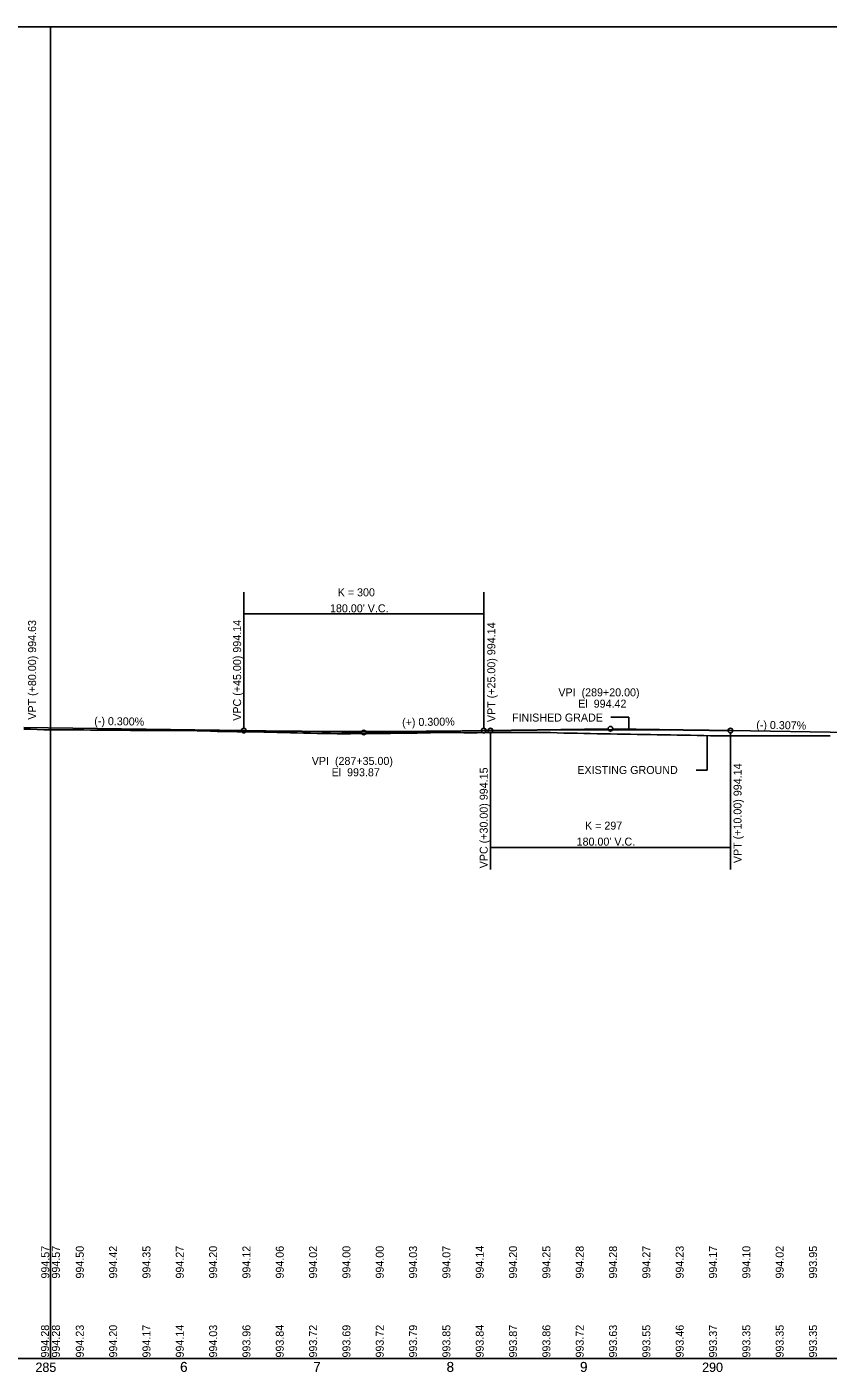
# Model space of a CAD drawing. Extents: x 1608361 to 16979326, y 1092015 to 12565288.
# Drawn here: x 16977468 to 16978069, y 12564278 to 12565286 of the extents above; entities that cross this region are included whole.
import ezdxf

# ---------------------------------------------------------------- set-up
doc = ezdxf.new("R2010")
doc.units = 0
for name, color, linetype in [('CLS_Median', 7, 'Continuous'), ('Default', 7, 'Continuous'), ('points EP', 7, 'Continuous'), ('RD_DDB_EX_Tx', 7, 'Continuous'), ('RD_EX_Fence_ChLk', 7, 'Continuous'), ('RD_EX_H2O', 7, 'Continuous'), ('RD_EX_RW_Approx', 7, 'Continuous'), ('RD_EX_SU_Water', 7, 'Continuous'), ('RD_EX_UT', 7, 'Continuous'), ('RD_HC_TX_Rel_Sta50', 7, 'Continuous'), ('RD_PD_Final_TX', 7, 'Continuous'), ('TEXT2', 7, 'Continuous')]:
    doc.layers.add(name, color=color, linetype=linetype)

msp = doc.modelspace()

# ---------------------------------------------------------------- linework, layer by layer
at = {"layer": 'CLS_Median'}
for p, q in [((16977906, 12564768.6), (16977919.4, 12564768.6)), ((16977919.4, 12564768.6), (16977919.4, 12564759.2))]:
    msp.add_line(p, q, dxfattribs=at)
at = {"layer": 'Default'}
for points in [[(16975985.6, 12564287.8), (16977485.6, 12564287.8), (16977485.6, 12565286), (16975985.6, 12565286)], [(16977485.6, 12564287.8), (16978985.6, 12564287.8), (16978985.6, 12565286), (16977485.6, 12565286)]]:
    msp.add_lwpolyline(points, close=True, dxfattribs=at)
at = {"layer": 'RD_DDB_EX_Tx'}
for p, q in [((16977978.2, 12564729), (16977978.2, 12564754.7)), ((16977970, 12564729), (16977978.2, 12564729))]:
    msp.add_line(p, q, dxfattribs=at)
at = {"layer": 'RD_EX_Fence_ChLk'}
for p, q in [((16977630.6, 12564862.3), (16977630.6, 12564760.2)), ((16977810.6, 12564862.3), (16977810.6, 12564760.2)), ((16977630.6, 12564846), (16977810.6, 12564846)), ((16977815.6, 12564654.3), (16977815.6, 12564756.8)), ((16977995.6, 12564654.3), (16977995.6, 12564756.8)), ((16977815.6, 12564671), (16977995.6, 12564671))]:
    msp.add_line(p, q, dxfattribs=at)
for centre in [(16977630.6, 12564758.5), (16977810.6, 12564758.5), (16977815.6, 12564758.5), (16977995.6, 12564758.5)]:
    msp.add_circle(centre, 1.75, dxfattribs=at)
at = {"layer": 'RD_EX_H2O'}
for points in [[(16977465.6, 12564759.6), (16977470.6, 12564759.5), (16977475.6, 12564759.3), (16977480.6, 12564759.2), (16977485.6, 12564759.2)], [(16977485.6, 12564759.2), (16977490.6, 12564759.1), (16977495.6, 12564759.1), (16977500.6, 12564759), (16977505.6, 12564759), (16977510.6, 12564759), (16977515.6, 12564758.9), (16977520.6, 12564758.9), (16977525.6, 12564758.9), (16977530.6, 12564758.8), (16977535.6, 12564758.8), (16977540.6, 12564758.8), (16977545.6, 12564758.7), (16977550.6, 12564758.7), (16977555.6, 12564758.7), (16977560.6, 12564758.7), (16977565.6, 12564758.6), (16977570.6, 12564758.6), (16977575.6, 12564758.6), (16977580.6, 12564758.5), (16977585.6, 12564758.5), (16977590.6, 12564758.5), (16977595.6, 12564758.4), (16977600.6, 12564758.3), (16977605.6, 12564758.1), (16977610.6, 12564757.9), (16977615.6, 12564757.9), (16977620.6, 12564757.8), (16977625.6, 12564757.7), (16977630.6, 12564757.6), (16977635.6, 12564757.6), (16977640.6, 12564757.5), (16977645.6, 12564757.4), (16977650.6, 12564757.3), (16977655.6, 12564757.2), (16977660.6, 12564757), (16977665.6, 12564756.9), (16977670.6, 12564756.8), (16977675.6, 12564756.6), (16977680.6, 12564756.5), (16977685.6, 12564756.4), (16977690.6, 12564756.4), (16977695.6, 12564756.3), (16977700.6, 12564756.2), (16977705.6, 12564756.2), (16977710.6, 12564756.2), (16977715.6, 12564756.3), (16977720.6, 12564756.3), (16977725.6, 12564756.3), (16977730.6, 12564756.3), (16977735.6, 12564756.4), (16977740.6, 12564756.4), (16977745.6, 12564756.6), (16977750.6, 12564756.7), (16977755.6, 12564756.7), (16977760.6, 12564756.7), (16977765.6, 12564756.8), (16977770.6, 12564756.9), (16977775.6, 12564757), (16977780.6, 12564757), (16977785.6, 12564757.1), (16977790.6, 12564757), (16977795.6, 12564756.9), (16977800.6, 12564756.9), (16977805.6, 12564756.9), (16977810.6, 12564757), (16977815.6, 12564757), (16977820.6, 12564757), (16977825.6, 12564757), (16977830.6, 12564757.1), (16977835.6, 12564757.1), (16977840.6, 12564757.1), (16977845.6, 12564757.1), (16977850.6, 12564757.1), (16977855.6, 12564757.1), (16977860.6, 12564757.1), (16977865.6, 12564756.9), (16977870.6, 12564756.7), (16977875.6, 12564756.6), (16977880.6, 12564756.5), (16977885.6, 12564756.4), (16977890.6, 12564756.3), (16977895.6, 12564756.2), (16977900.6, 12564756.1), (16977905.6, 12564756), (16977910.6, 12564755.9), (16977915.6, 12564755.9), (16977920.6, 12564755.8), (16977925.6, 12564755.7), (16977930.6, 12564755.6), (16977935.6, 12564755.5), (16977940.6, 12564755.4), (16977945.6, 12564755.3), (16977950.6, 12564755.3), (16977955.6, 12564755.2), (16977960.6, 12564755.1), (16977965.6, 12564755), (16977970.6, 12564754.9), (16977975.6, 12564754.8), (16977980.6, 12564754.7), (16977985.6, 12564754.7)], [(16977985.6, 12564754.7), (16977990.6, 12564754.6), (16977995.6, 12564754.5), (16978000.6, 12564754.5), (16978005.6, 12564754.5), (16978010.6, 12564754.5), (16978015.6, 12564754.5), (16978020.6, 12564754.5), (16978025.6, 12564754.5), (16978030.6, 12564754.5), (16978035.6, 12564754.5), (16978040.6, 12564754.5), (16978045.6, 12564754.5), (16978050.6, 12564754.5), (16978055.6, 12564754.5), (16978060.6, 12564754.5), (16978065.6, 12564754.5), (16978070.6, 12564754.5)]]:
    msp.add_lwpolyline(points, dxfattribs=at)
at = {"layer": 'RD_EX_RW_Approx'}
for p, q in [((16977630.6, 12564758.5), (16977718.8, 12564757.1)), ((16977810.5, 12564758.5), (16977722.3, 12564757.1)), ((16977815.6, 12564758.5), (16977903.8, 12564759.9)), ((16977995.5, 12564758.5), (16977907.3, 12564759.9))]:
    msp.add_line(p, q, dxfattribs=at)
for centre in [(16977720.6, 12564757.1), (16977905.6, 12564759.9)]:
    msp.add_circle(centre, 1.75, dxfattribs=at)
at = {"layer": 'RD_EX_UT'}
msp.add_line((16972985.6, 12564287.8), (16978789.9, 12564287.8), dxfattribs=at)
at = {"layer": 'RD_HC_TX_Rel_Sta50'}
for p, q in [((16977465.6, 12564760.9), (16977630.6, 12564758.5)), ((16977810.6, 12564758.5), (16977815.6, 12564758.5)), ((16977995.6, 12564758.5), (16978085.6, 12564757.1))]:
    msp.add_line(p, q, dxfattribs=at)
for points in [[(16977630.6, 12564758.5), (16977634.2, 12564758.4), (16977637.8, 12564758.4), (16977641.4, 12564758.3), (16977645, 12564758.3), (16977648.6, 12564758.2), (16977652.2, 12564758.2), (16977655.8, 12564758.1), (16977659.4, 12564758.1), (16977663, 12564758.1), (16977666.6, 12564758), (16977670.2, 12564758), (16977673.8, 12564758), (16977677.4, 12564757.9), (16977681, 12564757.9), (16977684.6, 12564757.9), (16977688.2, 12564757.9), (16977691.8, 12564757.9), (16977695.4, 12564757.8), (16977699, 12564757.8), (16977702.6, 12564757.8), (16977706.2, 12564757.8), (16977709.8, 12564757.8), (16977713.4, 12564757.8), (16977717, 12564757.8), (16977720.6, 12564757.8), (16977724.2, 12564757.8), (16977727.8, 12564757.8), (16977731.4, 12564757.8), (16977735, 12564757.8), (16977738.6, 12564757.8), (16977742.2, 12564757.8), (16977745.8, 12564757.8), (16977749.4, 12564757.9), (16977753, 12564757.9), (16977756.6, 12564757.9), (16977760.2, 12564757.9), (16977763.8, 12564757.9), (16977767.4, 12564758), (16977771, 12564758), (16977774.6, 12564758), (16977778.2, 12564758.1), (16977781.8, 12564758.1), (16977785.4, 12564758.1), (16977789, 12564758.2), (16977792.6, 12564758.2), (16977796.2, 12564758.3), (16977799.8, 12564758.3), (16977803.4, 12564758.4), (16977807, 12564758.4), (16977810.6, 12564758.5)], [(16977815.6, 12564758.5), (16977819.2, 12564758.6), (16977822.8, 12564758.6), (16977826.4, 12564758.7), (16977830, 12564758.7), (16977833.6, 12564758.8), (16977837.2, 12564758.8), (16977840.8, 12564758.9), (16977844.4, 12564758.9), (16977848, 12564758.9), (16977851.6, 12564759), (16977855.2, 12564759), (16977858.8, 12564759), (16977862.4, 12564759.1), (16977866, 12564759.1), (16977869.6, 12564759.1), (16977873.2, 12564759.1), (16977876.8, 12564759.1), (16977880.4, 12564759.2), (16977884, 12564759.2), (16977887.6, 12564759.2), (16977891.2, 12564759.2), (16977894.8, 12564759.2), (16977898.4, 12564759.2), (16977902, 12564759.2), (16977905.6, 12564759.2), (16977909.2, 12564759.2), (16977912.8, 12564759.2), (16977916.4, 12564759.2), (16977920, 12564759.2), (16977923.6, 12564759.2), (16977927.2, 12564759.2), (16977930.8, 12564759.2), (16977934.4, 12564759.1), (16977938, 12564759.1), (16977941.6, 12564759.1), (16977945.2, 12564759.1), (16977948.8, 12564759), (16977952.4, 12564759), (16977956, 12564759), (16977959.6, 12564759), (16977963.2, 12564758.9), (16977966.8, 12564758.9), (16977970.4, 12564758.8), (16977974, 12564758.8), (16977977.6, 12564758.8), (16977981.2, 12564758.7), (16977984.8, 12564758.7), (16977988.4, 12564758.6), (16977992, 12564758.6), (16977995.6, 12564758.5)]]:
    msp.add_spline(points, degree=3, dxfattribs=at)

# ---------------------------------------------------------------- texts
at = {"layer": 'CLS_Median'}
msp.add_text('FINISHED GRADE', height=6, dxfattribs=at).set_placement((16977831.8, 12564765.3))
at = {"layer": 'points EP'}
for s, rotation, p in [('(-) 0.300%', 359.1406, (16977518.4, 12564762.8)), ('(+) 0.300%', 0.8594, (16977749.4, 12564761.8)), ('(-) 0.307%', 359.1208, (16978015, 12564759.9))]:
    msp.add_text(s, height=6, rotation=rotation, dxfattribs=at).set_placement(p)
at = {"layer": 'RD_DDB_EX_Tx'}
msp.add_text('EXISTING GROUND', height=6, dxfattribs=at).set_placement((16977880.8, 12564726))
at = {"layer": 'RD_EX_Fence_ChLk'}
for s, p in [('K = 300', (16977701.1, 12564859.2)), ("180.00' V.C.", (16977695.3, 12564847.2)), ('K = 297', (16977886.6, 12564684.3)), ("180.00' V.C.", (16977880.3, 12564672.3))]:
    msp.add_text(s, height=6, dxfattribs=at).set_placement(p)
for s, p in [('VPT (+80.00) 994.63', (16977474.8, 12564766.7)), ('VPC (+45.00) 994.14', (16977628.6, 12564765.9)), ('VPT (+25.00) 994.14', (16977819.3, 12564764.9)), ('VPC (+30.00) 994.15', (16977813.6, 12564655.3)), ('VPT (+10.00) 994.14', (16978004, 12564659.2))]:
    msp.add_text(s, height=6, rotation=90, dxfattribs=at).set_placement(p)
at = {"layer": 'RD_EX_RW_Approx'}
for s, p in [('VPI  (289+20.00)', (16977866.6, 12564784.2)), ('El  994.42', (16977881.5, 12564775.7)), ('VPI  (287+35.00)', (16977681.6, 12564732.8)), ('El  993.87', (16977696.5, 12564724.3))]:
    msp.add_text(s, height=6, dxfattribs=at).set_placement(p)
at = {"layer": 'RD_EX_SU_Water'}
for s, p in [('994.57', (16977484.7, 12564347.8)), ('994.57', (16977492.7, 12564347.8)), ('994.50', (16977510.6, 12564347.8)), ('994.42', (16977535.6, 12564347.8)), ('994.35', (16977560.6, 12564347.8)), ('994.27', (16977585.6, 12564347.8)), ('994.20', (16977610.6, 12564347.8)), ('994.12', (16977635.6, 12564347.8)), ('994.06', (16977660.6, 12564347.8)), ('994.02', (16977685.6, 12564347.8)), ('994.00', (16977710.6, 12564347.8)), ('994.00', (16977735.6, 12564347.8)), ('994.03', (16977760.6, 12564347.8)), ('994.07', (16977785.6, 12564347.8)), ('994.14', (16977810.6, 12564347.8)), ('994.20', (16977835.6, 12564347.8)), ('994.25', (16977860.6, 12564347.8)), ('994.28', (16977885.6, 12564347.8)), ('994.28', (16977910.6, 12564347.8)), ('994.27', (16977935.6, 12564347.8)), ('994.23', (16977960.6, 12564347.8)), ('994.17', (16977985.6, 12564347.8)), ('994.10', (16978010.6, 12564347.8)), ('994.02', (16978035.6, 12564347.8)), ('993.95', (16978060.6, 12564347.8))]:
    msp.add_text(s, height=6, rotation=90, dxfattribs=at).set_placement(p)
at = {"layer": 'RD_PD_Final_TX'}
for s, height, p in [('285', 7, (16977474.3, 12564277.8)), ('285', 7, (16977474.4, 12564277.8)), ('6', 7.5, (16977582.8, 12564277.8)), ('6', 7.5, (16977582.9, 12564277.8)), ('7', 7.5, (16977682.7, 12564277.8)), ('7', 7.5, (16977682.8, 12564277.8)), ('8', 7.5, (16977782.7, 12564277.8)), ('8', 7.5, (16977782.8, 12564277.8)), ('9', 7.5, (16977882.8, 12564277.8)), ('9', 7.5, (16977882.9, 12564277.8)), ('290', 7, (16977974.4, 12564277.8)), ('290', 7, (16977974.5, 12564277.8))]:
    msp.add_text(s, height=height, dxfattribs=at).set_placement(p)
at = {"layer": 'TEXT2'}
for s, p in [('994.28', (16977484.5, 12564288.6)), ('994.28', (16977492.7, 12564288.6)), ('994.23', (16977510.6, 12564288.6)), ('994.20', (16977535.6, 12564288.6)), ('994.17', (16977560.6, 12564288.6)), ('994.14', (16977585.6, 12564288.6)), ('994.03', (16977610.6, 12564288.6)), ('993.96', (16977635.6, 12564288.6)), ('993.84', (16977660.6, 12564288.6)), ('993.72', (16977685.6, 12564288.6)), ('993.69', (16977710.6, 12564288.6)), ('993.72', (16977735.6, 12564288.6)), ('993.79', (16977760.6, 12564288.6)), ('993.85', (16977785.6, 12564288.6)), ('993.84', (16977810.6, 12564288.6)), ('993.87', (16977835.6, 12564288.6)), ('993.86', (16977860.6, 12564288.6)), ('993.72', (16977885.6, 12564288.6)), ('993.63', (16977910.6, 12564288.6)), ('993.55', (16977935.6, 12564288.6)), ('993.46', (16977960.6, 12564288.6)), ('993.37', (16977985.6, 12564288.6)), ('993.35', (16978010.6, 12564288.6)), ('993.35', (16978035.6, 12564288.6)), ('993.35', (16978060.6, 12564288.6))]:
    msp.add_text(s, height=6, rotation=90, dxfattribs=at).set_placement(p)

doc.saveas('drawing.dxf')
